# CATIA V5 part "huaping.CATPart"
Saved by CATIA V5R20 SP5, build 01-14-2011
Part number: 花瓶
Material "Gold": density 19320 kg/m3, Young's modulus 7.8e+10 Pa, Poisson ratio 0.42, thermal expansion 1.42e-05 1/K
Bounding box of the stored display mesh (mm): x -30 to 30, y -30 to 29.969, z 0 to 114.381
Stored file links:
  E:\3.8  3D工程绘图\huaping.CATPart
  C:\Program Files\Dassault Systemes\B20\intel_a\startup\materials\Catalog.CATMaterial
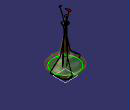
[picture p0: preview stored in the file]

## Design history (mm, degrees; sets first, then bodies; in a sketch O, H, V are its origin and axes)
Body1 (main body), material "Gold"
  Plane1: type Offset, RefPlane xy-plane, Offset 10
  Plane2: type Offset, RefPlane Plane1, Offset 10
  Plane3: type Offset, RefPlane Plane2, Offset 10
  Plane4: type Offset, RefPlane Plane3, Offset 10
  Plane5: type Offset, RefPlane Plane4, Offset 10
  Plane6: type Offset, RefPlane Plane5, Offset 10
  Plane7: type Offset, RefPlane Plane6, Offset 10
  Plane8: type Offset, RefPlane Plane7, Offset 10
  Plane9: type Offset, RefPlane Plane8, Offset 10
  Sketch1 on xy-plane, origin (0, 0, 0), H (1, 0, 0), V (0, 1, 0)
    circle A1 centre (0, 0) radius 10
    radius A1 = 10
  Sketch2 on Plane1, origin (0, 0, 10), H (1, 0, 0), V (0, 1, 0)
    circle A1 centre (0, 0) radius 20
    radius A1 = 20
  Sketch3 on Plane2, origin (0, 0, 20), H (1, 0, 0), V (0, 1, 0)
    circle A1 centre (0, 0) radius 30
    radius A1 = 30
  Sketch4 on Plane3, origin (0, 0, 30), H (1, 0, 0), V (0, 1, 0)
    circle A1 centre (0, 0) radius 20
    point P1 (20, 0)
    radius A1 = 20
    coincidence: A1 P1, P1 H
  Sketch5 on Plane4, origin (0, 0, 40), H (1, 0, 0), V (0, 1, 0)
    circle A1 centre (0, 0) radius 10
    radius A1 = 10
  Sketch6 on Plane5, origin (0, 0, 50), H (1, 0, 0), V (0, 1, 0)
    circle A1 centre (0, 0) radius 7.5
    radius A1 = 7.5
  Sketch7 on Plane6, origin (0, 0, 60), H (1, 0, 0), V (0, 1, 0)
    circle A1 centre (0, 0) radius 5
    radius A1 = 5
  Sketch8 on Plane7, origin (0, 0, 70), H (1, 0, 0), V (0, 1, 0)
    circle A1 centre (0, 0) radius 3.5
    radius A1 = 3.5
  Sketch9 on Plane8, origin (0, 0, 80), H (1, 0, 0), V (0, 1, 0)
    circle A1 centre (0, 0) radius 3.5
    radius A1 = 3.5
  Sketch10 on Plane9, origin (0, 0, 90), H (1, 0, 0), V (0, 1, 0)
    circle A1 centre (0, 0) radius 6
    radius A1 = 6
  Loft1: solid, Sections (Sketch1; Sketch2; Sketch3; Sketch4; Sketch5; Sketch6; Sketch7; Sketch8; Sketch9; Sketch10)
  Shell1: ExtOffset 0, Face face of Loft1, IntOffset 1
Body2
  Sketch11 on yz-plane, origin (0, 0, 0), H (0, 1, 0), V (0, 0, 1)
    axis line L1 (0, 96.8403) -> (0, -9.625)
    point P1 (0, 96.8403)
    line L2 (0, 17.7348) -> (24.6956, 17.7348)
    point P3 (0, 17.7348)
    point P4 (24.6956, 17.7348)
    spline S1 through (24.6956, 17.7348) (15.8957, 8.2183) (6.7976, 2.5679)
    line L3 (6.7976, 2.5679) -> (0, 2.5679)
    point P5 (6.7976, 2.5679)
    point P6 (0, 2.5679)
    point P7 (24.6956, 17.7348)
    point P8 (6.7976, 2.5679)
    coincidence: P1 V, P3 L1, P7 P4, P8 P5, P6 L1
    vertical: L1 V
    horizontal: L2 H, L3 H
  Shaft1: profile Sketch11, axis Sketch11.L1, angle 360
Body3
  Sketch12 on yz-plane, origin (0, 0, 0), H (0, 1, 0), V (0, 0, 1)
    spline S1 through (-2.3005, 4.2035) (1.8757, 97.8812) (3.0689, 103.6803)
  Plane10: type Normal, Curve Sketch12, RefPoint vertex of Sketch12
  Sketch13 on Plane10, origin (0, 21.4905, 99.7099), H (1, 0, 0), V (0, -0.9776, 0.2107)
    circle A1 centre (0, 18.8103) radius 0.25
    point P1 (0, 18.8103)
    radius A1 = 0.25
    coincidence: P1 V
  Rib1: profile Sketch13, centre curve Sketch12
  Sketch14 on face of Rib1, origin (0, 21.4905, 99.7099), H (-1, 0, 0), V (0, -0.9776, 0.2107)
    spline S1 through (0, 20.6238) (-1.7869, 21.9337) (-3.2585, 20.6238) (-1.7869, 18.0564) (0, 17.1657) (1.5767, 18.0564) (2.9957, 20.6238) (1.5767, 21.9337) (0, 20.6238)
    point P1 (0, 20.6238)
    point P2 (0, 17.1657)
    point P3 (0, 20.6238)
    coincidence: P1 V, P2 V, P3 P1
  Pad1: profile Sketch14, direction (0, 0.2107, 0.9776), length 0.1
Body4
  Sketch15 on yz-plane, origin (0, 0, 0), H (0, 1, 0), V (0, 0, 1)
    spline S1 through (0.944, 5.9979) (0.944, 78.0675) (-10.7112, 113.3415)
  Plane11: type Normal, Curve Sketch15, RefPoint vertex of Sketch15
  Sketch16 on Plane11, origin (0, -44.2851, 98.2009), H (1, 0, 0), V (0, 0.9116, 0.4111)
    circle A1 centre (0, 36.8091) radius 0.25
    point P1 (0, 36.8091)
    radius A1 = 0.25
    coincidence: P1 V
  Rib2: profile Sketch16, centre curve Sketch15
  Sketch17 on Plane11, origin (0, -44.2851, 98.2009), H (1, 0, 0), V (0, 0.9116, 0.4111)
    spline S1 through (0, 38.2007) (-1.3685, 39.1374) (-2.7778, 38.2007) (-1.3685, 35.8123) (0, 34.8756) (1.3091, 35.8123) (2.4366, 38.2007) (1.3091, 39.1374) (0, 38.2007)
    point P1 (0, 38.2007)
    point P2 (0, 34.8756)
    point P3 (0, 38.2007)
    coincidence: P1 V, P2 V, P3 P1
  Pad2: profile Sketch17, direction (0, -0.4111, 0.9116), length 0.1
Body5
  Sketch18 on zx-plane, origin (0, 0, 0), H (-1, 0, 0), V (0, 0, 1)
    spline S1 through (-5.3144, 11.7448) (3.7399, 96.1163) (7.6203, 108.8273)
  Plane12: type Normal, Curve Sketch18, RefPoint vertex of Sketch18
  Sketch19 on Plane12, origin (-33.4073, 0, 100.2326), H (0, 1, 0), V (0.9487, 0, 0.3162)
    circle A1 centre (0, 26.9443) radius 0.25
    point P1 (0, 26.9443)
    radius A1 = 0.25
    coincidence: P1 V
  Rib3: profile Sketch19, centre curve Sketch18
  Sketch20 on Plane12, origin (-33.4073, 0, 100.2326), H (0, 1, 0), V (0.9487, 0, 0.3162)
    spline S1 through (0, 29.541) (-2.8266, 31.0589) (-5.8716, 29.541) (-2.8266, 25.6379) (0, 24.3369) (2.6109, 25.6379) (4.1334, 29.541) (2.6109, 31.0589) (0, 29.541)
    point P1 (0, 29.541)
    point P2 (0, 24.3369)
    point P3 (0, 29.541)
    coincidence: P1 V, P2 V, P3 P1
  Pad3: profile Sketch20, direction (0.3162, 0, -0.9487), length 0.1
